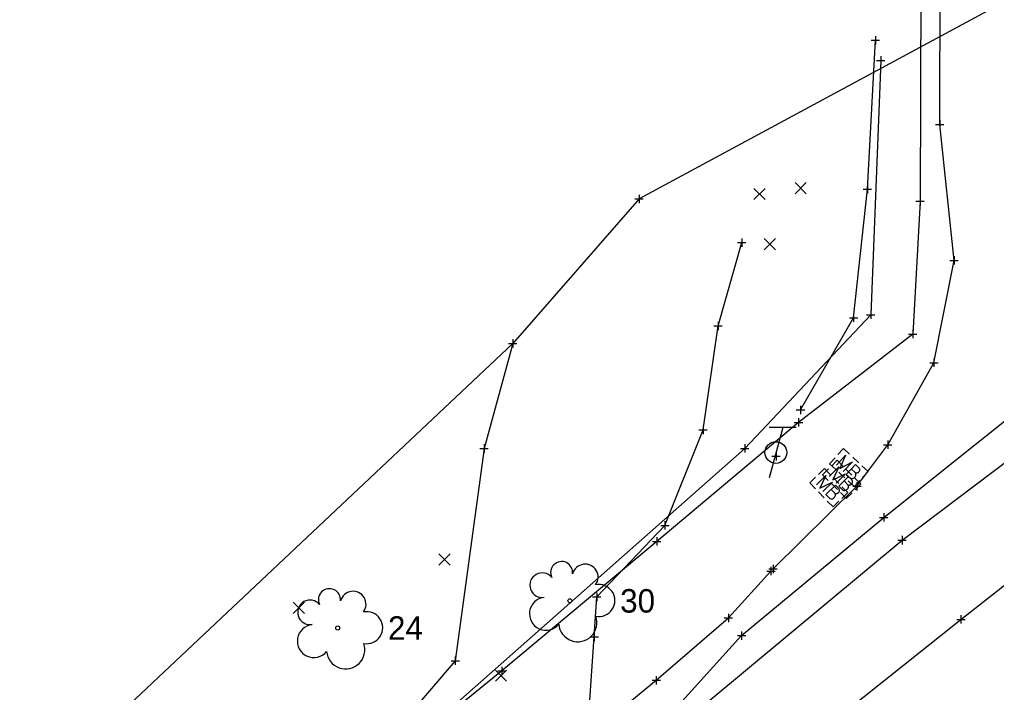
# Model space of a CAD drawing. Extents: x 2184635 to 2185378, y 369880 to 370486.
# Drawn here: x 2184907.9 to 2185024.5, y 370185.8 to 370266 of the extents above; entities that cross this region are included whole.
import ezdxf

# ---------------------------------------------------------------- set-up
doc = ezdxf.new("R2010")
doc.units = 0
for name, color, linetype in [('_CIVIL_CONSTRUCTION', 7, 'Continuous'), ('GE_X_Alignment', 7, 'Continuous'), ('GE_X_Alignment_100_Distances', 7, 'Continuous'), ('PM_X_CL_Pass_Proh_Rt', 7, 'Continuous'), ('PM_X_Edge_Line', 7, 'Continuous'), ('PV_X_COP', 7, 'Continuous'), ('PV_X_Driveway', 7, 'Continuous'), ('PV_X_EOP', 7, 'Continuous'), ('PV_X_Shoulder', 7, 'Continuous'), ('RD_X_Fence', 7, 'Continuous'), ('RW_X_CL', 7, 'Continuous'), ('RW_X_CL_100_Cardinal_Points', 7, 'Continuous'), ('RW_X_CL_100_Distances', 7, 'Continuous'), ('SV_X_Break_Lines', 7, 'Continuous'), ('SV_X_Terrain_Boundary', 7, 'Continuous'), ('VG_X_Text', 7, 'Continuous'), ('VG_X_Tree_Line_Lt', 7, 'Continuous')]:
    doc.layers.add(name, color=color, linetype=linetype)

msp = doc.modelspace()

# ---------------------------------------------------------------- linework, layer by layer
at = {"layer": '_CIVIL_CONSTRUCTION'}
for p, q in [((2185000.47, 370245.24), (2185001.8, 370246.58)), ((2185000.47, 370246.58), (2185001.8, 370245.24)), ((2184995.55, 370244.55), (2184996.88, 370245.89)), ((2184995.55, 370245.89), (2184996.88, 370244.55)), ((2184996.77, 370238.57), (2184998.11, 370239.9)), ((2184996.77, 370239.9), (2184998.11, 370238.57)), ((2184957.94, 370200.95), (2184959.27, 370202.28)), ((2184957.94, 370202.28), (2184959.27, 370200.95)), ((2184940.54, 370195.19), (2184941.88, 370196.52)), ((2184940.54, 370196.52), (2184941.88, 370195.19)), ((2184964.7, 370187.1), (2184966.03, 370188.43)), ((2184964.7, 370188.43), (2184966.03, 370187.1))]:
    msp.add_line(p, q, dxfattribs=at)
at = {"layer": 'GE_X_Alignment'}
for centre in [(2184973.58, 370196.69), (2184945.86, 370193.45)]:
    msp.add_circle(centre, 0.24, dxfattribs=at)
for centre, radius, start, end in [((2184972.59, 370200.06), 1.32, 354.0047, 205.9741), ((2184975.4, 370199.52), 1.55, 323.83, 165.0376), ((2184970.27, 370198.56), 1.47, 39.0625, 279.5412), ((2184977.04, 370196.73), 1.91, 259.1453, 101.4596), ((2184944.88, 370196.82), 1.32, 354.0047, 205.9741), ((2184947.69, 370196.28), 1.55, 323.83, 165.0376), ((2184942.55, 370195.32), 1.47, 39.0625, 279.5412), ((2184970.72, 370195.15), 1.97, 96.1722, 320.5737), ((2184949.32, 370193.49), 1.91, 259.1453, 101.4596), ((2184943.01, 370191.9), 1.97, 96.1722, 320.5737), ((2184974.52, 370194.09), 2.28, 184.9476, 19.4572), ((2184946.81, 370190.85), 2.28, 184.9476, 19.4572)]:
    msp.add_arc(centre, radius, start, end, dxfattribs=at)
at = {"layer": 'GE_X_Alignment_100_Distances'}
msp.add_lwpolyline([(2184659.61, 369925.95), (2184700.37, 369957.79), (2184738.5, 369988.63), (2184777.83, 370020.25), (2184816.43, 370051.35), (2184855.55, 370082.58), (2184897, 370115.36), (2184935.6, 370145.23), (2184944.92, 370153.84), (2184957.87, 370164.57), (2184961.94, 370169.28), (2184974.73, 370179.72), (2184983.89, 370187.22), (2184992.5, 370194.66), (2184997.57, 370200.25)], dxfattribs=at)
at = {"layer": 'PM_X_CL_Pass_Proh_Rt'}
msp.add_lwpolyline([(2184772.08, 369998.33), (2184786.36, 370009.44), (2184824.96, 370040.26), (2184864.24, 370071.89), (2184905.97, 370104.8), (2184943.4, 370134), (2184983.48, 370165.21), (2185020.26, 370194.47), (2185061.22, 370226.63), (2185099.74, 370257.78), (2185139.18, 370289.51), (2185177.35, 370320.31), (2185216.05, 370351.8), (2185254.73, 370383.45)], dxfattribs=at)
at = {"layer": 'PM_X_Edge_Line'}
msp.add_lwpolyline([(2184661.52, 369922.95), (2184702.12, 369955.42), (2184740.46, 369986.31), (2184779.79, 370018.04), (2184818.42, 370048.83), (2184857.46, 370080.19), (2184899.14, 370112.8), (2184937.36, 370142.73), (2184976.78, 370173.64), (2185013.23, 370203.93), (2185054.74, 370235.21), (2185093.13, 370266.2), (2185132.9, 370298.21), (2185170.88, 370328.99), (2185209.71, 370360.44), (2185248.24, 370392.05)], dxfattribs=at)
at = {"layer": 'PV_X_COP'}
msp.add_lwpolyline([(2184667.94, 369914.54), (2184708.44, 369946.75), (2184746.44, 369977.52), (2184786.36, 370009.44), (2184824.96, 370040.26), (2184864.24, 370071.89), (2184905.97, 370104.8), (2184943.4, 370134), (2184983.48, 370165.21), (2185020.26, 370194.47), (2185061.22, 370226.63), (2185099.74, 370257.78), (2185139.18, 370289.51), (2185177.35, 370320.31), (2185216.05, 370351.8), (2185254.68, 370383.2)], dxfattribs=at)
at = {"layer": 'PV_X_Driveway'}
msp.add_lwpolyline([(2184997.84, 370200.5), (2185007.85, 370210.36), (2185011.52, 370215.32), (2185017.04, 370225.09), (2185019.44, 370237.31), (2185017.73, 370253.53), (2185017.77, 370271.02), (2185017.83, 370279.15)], dxfattribs=at)
at = {"layer": 'PV_X_EOP'}
msp.add_lwpolyline([(2184661.56, 369922.86), (2184702.12, 369955.42), (2184740.46, 369986.31), (2184779.79, 370018.04), (2184818.42, 370048.83), (2184857.46, 370080.19), (2184899.14, 370112.8), (2184937.36, 370142.73), (2184976.78, 370173.64), (2185013.23, 370203.93), (2185054.74, 370235.21), (2185093.13, 370266.2), (2185132.9, 370298.21), (2185170.88, 370328.99), (2185209.71, 370360.44), (2185248.18, 370392.04)], dxfattribs=at)
at = {"layer": 'PV_X_Shoulder'}
msp.add_lwpolyline([(2184660.62, 369924.65), (2184701.18, 369956.99), (2184739.31, 369987.69), (2184778.66, 370019.08), (2184817.14, 370050.2), (2184856.42, 370081.4), (2184897.96, 370114.28), (2184936.32, 370143.73), (2184975.81, 370174.82), (2184986.61, 370184.31), (2184994.08, 370192.55), (2185011.04, 370206.65), (2185033.17, 370224.29), (2185051.81, 370238.9), (2185062.89, 370246.96), (2185064.96, 370248), (2185067.33, 370248.11), (2185092.06, 370267.24), (2185132, 370299.51), (2185169.97, 370330.25), (2185208.84, 370361.61), (2185247.24, 370392.98)], dxfattribs=at)
at = {"layer": 'RD_X_Fence'}
msp.add_lwpolyline([(2185015.2, 370283.15), (2185015.46, 370270.12), (2185015.39, 370244.36), (2185014.51, 370228.51), (2185000.87, 370217.98), (2184983.95, 370203.78), (2184965.47, 370188.33), (2184938.37, 370166.29), (2184905.93, 370138.5), (2184906.07, 370146.45), (2184906.53, 370163.61)], dxfattribs=at)
at = {"layer": 'RW_X_CL'}
for p, q in [((2185010.05, 370264.07), (2185010.05, 370263.07)), ((2185009.55, 370263.57), (2185010.55, 370263.57)), ((2185010.05, 370263.57), (2185010.05, 370263.57)), ((2185010.68, 370261.65), (2185010.68, 370260.65)), ((2185010.18, 370261.15), (2185011.18, 370261.15)), ((2185010.68, 370261.15), (2185010.68, 370261.15)), ((2185017.23, 370253.53), (2185018.23, 370253.53)), ((2185017.73, 370254.03), (2185017.73, 370253.03)), ((2185017.73, 370253.53), (2185017.73, 370253.53)), ((2185008.59, 370245.79), (2185009.59, 370245.79)), ((2185009.09, 370246.29), (2185009.09, 370245.29)), ((2185009.09, 370245.79), (2185009.09, 370245.79)), ((2184981.34, 370244.63), (2184982.34, 370244.63)), ((2184981.84, 370245.13), (2184981.84, 370244.13)), ((2184981.84, 370244.63), (2184981.84, 370244.63)), ((2185014.89, 370244.36), (2185015.89, 370244.36)), ((2185015.39, 370244.86), (2185015.39, 370243.86)), ((2185015.39, 370244.36), (2185015.39, 370244.36)), ((2184993.6, 370239.43), (2184994.6, 370239.43)), ((2184994.1, 370239.93), (2184994.1, 370238.93)), ((2184994.1, 370239.43), (2184994.1, 370239.43)), ((2185018.94, 370237.31), (2185019.94, 370237.31)), ((2185019.44, 370237.81), (2185019.44, 370236.81)), ((2185019.44, 370237.31), (2185019.44, 370237.31)), ((2185009.5, 370231.33), (2185009.5, 370230.33)), ((2185006.95, 370230.47), (2185007.95, 370230.47)), ((2185007.45, 370230.97), (2185007.45, 370229.97)), ((2185007.45, 370230.47), (2185007.45, 370230.47)), ((2185009, 370230.83), (2185010, 370230.83)), ((2185009.5, 370230.83), (2185009.5, 370230.83)), ((2184990.77, 370229.49), (2184991.77, 370229.49)), ((2184991.27, 370229.99), (2184991.27, 370228.99)), ((2184991.27, 370229.49), (2184991.27, 370229.49)), ((2185014.51, 370229.01), (2185014.51, 370228.01)), ((2184966.76, 370227.91), (2184966.76, 370226.91)), ((2185014.01, 370228.51), (2185015.01, 370228.51)), ((2185014.51, 370228.51), (2185014.51, 370228.51)), ((2184966.26, 370227.41), (2184967.26, 370227.41)), ((2184966.76, 370227.41), (2184966.76, 370227.41)), ((2185017.04, 370225.59), (2185017.04, 370224.59)), ((2185016.54, 370225.09), (2185017.54, 370225.09)), ((2185017.04, 370225.09), (2185017.04, 370225.09)), ((2185001.11, 370219.96), (2185001.11, 370218.96)), ((2185000.61, 370219.46), (2185001.61, 370219.46)), ((2185000.87, 370218.48), (2185000.87, 370217.48)), ((2185001.11, 370219.46), (2185001.11, 370219.46)), ((2184989.47, 370217.58), (2184989.47, 370216.58)), ((2185000.37, 370217.98), (2185001.37, 370217.98)), ((2185000.87, 370217.98), (2185000.87, 370217.98)), ((2184988.97, 370217.08), (2184989.97, 370217.08)), ((2184989.47, 370217.08), (2184989.47, 370217.08)), ((2184962.84, 370214.87), (2184963.84, 370214.87)), ((2184963.34, 370215.37), (2184963.34, 370214.37)), ((2184963.34, 370214.87), (2184963.34, 370214.87)), ((2184993.95, 370214.87), (2184994.95, 370214.87)), ((2184994.45, 370215.37), (2184994.45, 370214.37)), ((2184994.45, 370214.87), (2184994.45, 370214.87)), ((2185011.02, 370215.32), (2185012.02, 370215.32)), ((2185011.52, 370215.82), (2185011.52, 370214.82)), ((2185011.52, 370215.32), (2185011.52, 370215.32)), ((2184997.7, 370213.94), (2184998.7, 370213.94)), ((2184998.2, 370214.44), (2184998.2, 370213.44)), ((2184998.2, 370213.94), (2184998.2, 370213.94)), ((2185007.35, 370210.36), (2185008.35, 370210.36)), ((2185007.85, 370210.86), (2185007.85, 370209.86)), ((2185007.85, 370210.36), (2185007.85, 370210.36)), ((2185011.04, 370207.15), (2185011.04, 370206.15)), ((2184984.42, 370205.69), (2184985.42, 370205.69)), ((2184984.92, 370206.19), (2184984.92, 370205.19)), ((2184984.92, 370205.69), (2184984.92, 370205.69)), ((2185010.54, 370206.65), (2185011.54, 370206.65)), ((2185011.04, 370206.65), (2185011.04, 370206.65)), ((2185013.23, 370204.43), (2185013.23, 370203.43)), ((2185013.23, 370204.43), (2185013.23, 370203.43)), ((2184983.45, 370203.78), (2184984.45, 370203.78)), ((2184983.95, 370204.28), (2184983.95, 370203.28)), ((2184983.95, 370203.78), (2184983.95, 370203.78)), ((2185012.73, 370203.93), (2185013.73, 370203.93)), ((2185012.73, 370203.93), (2185013.73, 370203.93)), ((2185013.23, 370203.93), (2185013.23, 370203.93)), ((2185013.23, 370203.93), (2185013.23, 370203.93)), ((2184997.84, 370201), (2184997.84, 370200)), ((2184997.07, 370200.25), (2184998.07, 370200.25)), ((2184997.34, 370200.5), (2184998.34, 370200.5)), ((2184997.57, 370200.75), (2184997.57, 370199.75)), ((2184997.57, 370200.25), (2184997.57, 370200.25)), ((2184997.84, 370200.5), (2184997.84, 370200.5)), ((2184976.78, 370197.65), (2184976.78, 370196.65)), ((2184976.28, 370197.15), (2184977.28, 370197.15)), ((2184976.78, 370197.15), (2184976.78, 370197.15)), ((2184992.5, 370195.16), (2184992.5, 370194.16)), ((2184992, 370194.66), (2184993, 370194.66)), ((2184992.5, 370194.66), (2184992.5, 370194.66)), ((2185019.76, 370194.47), (2185020.76, 370194.47)), ((2185019.76, 370194.47), (2185020.76, 370194.47)), ((2185020.26, 370194.97), (2185020.26, 370193.97)), ((2185020.26, 370194.97), (2185020.26, 370193.97)), ((2185020.26, 370194.47), (2185020.26, 370194.47)), ((2185020.26, 370194.47), (2185020.26, 370194.47)), ((2184976.49, 370192.88), (2184976.49, 370191.88)), ((2184994.08, 370193.05), (2184994.08, 370192.05)), ((2184975.99, 370192.38), (2184976.99, 370192.38)), ((2184976.49, 370192.38), (2184976.49, 370192.38)), ((2184993.58, 370192.55), (2184994.58, 370192.55)), ((2184994.08, 370192.55), (2184994.08, 370192.55)), ((2184959.4, 370189.55), (2184960.4, 370189.55)), ((2184959.9, 370190.05), (2184959.9, 370189.05)), ((2184959.9, 370189.55), (2184959.9, 370189.55)), ((2184964.97, 370188.33), (2184965.97, 370188.33)), ((2184965.47, 370188.83), (2184965.47, 370187.83)), ((2184965.47, 370188.33), (2184965.47, 370188.33)), ((2184983.39, 370187.22), (2184984.39, 370187.22)), ((2184983.89, 370187.72), (2184983.89, 370186.72)), ((2184983.89, 370187.22), (2184983.89, 370187.22))]:
    msp.add_line(p, q, dxfattribs=at)
at = {"layer": 'RW_X_CL_100_Cardinal_Points'}
for p, q in [((2185007.34, 370213.83), (2185008.07, 370213.15)), ((2185006.88, 370212.59), (2185006.88, 370212.59)), ((2185005, 370211.4), (2185005.7, 370210.68)), ((2185005.67, 370212.04), (2185006.41, 370211.36)), ((2185006.53, 370212.41), (2185007.24, 370211.7)), ((2185004.48, 370210.18), (2185004.48, 370210.18)), ((2185004.8, 370210.68), (2185005.51, 370209.97)), ((2185006.03, 370211.18), (2185006.03, 370211.18)), ((2185003.25, 370209.69), (2185003.95, 370208.97))]:
    msp.add_line(p, q, dxfattribs=at)
for points in [[(2185005.58, 370214.13), (2185006.24, 370214.85), (2185006.96, 370214.19)], [(2185005.29, 370212.39), (2185004.58, 370213.05), (2185005.24, 370213.76)], [(2185005.39, 370212.88), (2185006.47, 370214.06), (2185005.81, 370212.49), (2185007.3, 370213.29), (2185006.22, 370212.11)], [(2185004.54, 370211.53), (2185005.68, 370212.66), (2185004.95, 370211.12), (2185006.48, 370211.86), (2185005.35, 370210.73)], [(2185004.79, 370212.77), (2185005.48, 370213.46), (2185006.16, 370212.77)], [(2185007.68, 370211.95), (2185007.77, 370211.95), (2185007.82, 370211.95), (2185007.86, 370211.96), (2185007.89, 370211.97), (2185007.94, 370211.99), (2185007.98, 370212.01), (2185008.06, 370212.06), (2185008.08, 370212.09), (2185008.12, 370212.12), (2185008.16, 370212.19), (2185008.18, 370212.25), (2185008.19, 370212.31), (2185008.18, 370212.39), (2185008.16, 370212.45), (2185008.15, 370212.47), (2185008.12, 370212.53), (2185007.67, 370212.95), (2185006.58, 370211.78), (2185007.09, 370211.31), (2185007.18, 370211.29), (2185007.28, 370211.28), (2185007.4, 370211.31), (2185007.5, 370211.37), (2185007.59, 370211.44), (2185007.64, 370211.5), (2185007.67, 370211.57), (2185007.71, 370211.69), (2185007.72, 370211.79), (2185007.68, 370211.95), (2185007.17, 370212.42)], [(2185008.45, 370212.8), (2185009.18, 370212.13), (2185008.52, 370211.41)], [(2185002.89, 370210.06), (2185002.21, 370210.76), (2185002.9, 370211.43)], [(2185003, 370210.55), (2185004.15, 370211.66), (2185003.41, 370210.13), (2185004.94, 370210.85), (2185003.79, 370209.73)], [(2185003.26, 370211.78), (2185003.96, 370212.46), (2185004.64, 370211.77)], [(2185004.43, 370211.05), (2185003.75, 370211.73), (2185004.44, 370212.42)], [(2185006.8, 370210.51), (2185006.89, 370210.51), (2185006.94, 370210.51), (2185006.99, 370210.52), (2185007.01, 370210.53), (2185007.07, 370210.54), (2185007.1, 370210.56), (2185007.18, 370210.61), (2185007.21, 370210.63), (2185007.24, 370210.67), (2185007.29, 370210.73), (2185007.32, 370210.79), (2185007.32, 370210.86), (2185007.32, 370210.94), (2185007.3, 370210.99), (2185007.29, 370211.02), (2185007.26, 370211.08), (2185006.83, 370211.52), (2185005.69, 370210.38), (2185006.18, 370209.89), (2185006.28, 370209.87), (2185006.38, 370209.86), (2185006.5, 370209.89), (2185006.6, 370209.94), (2185006.69, 370210.01), (2185006.74, 370210.06), (2185006.78, 370210.13), (2185006.83, 370210.25), (2185006.83, 370210.35), (2185006.8, 370210.51), (2185006.31, 370211)], [(2185005.24, 370209.49), (2185005.33, 370209.49), (2185005.38, 370209.49), (2185005.43, 370209.5), (2185005.46, 370209.51), (2185005.51, 370209.53), (2185005.55, 370209.54), (2185005.63, 370209.59), (2185005.65, 370209.61), (2185005.69, 370209.65), (2185005.73, 370209.71), (2185005.76, 370209.77), (2185005.77, 370209.83), (2185005.76, 370209.91), (2185005.75, 370209.97), (2185005.74, 370209.99), (2185005.71, 370210.06), (2185005.28, 370210.5), (2185004.14, 370209.38), (2185004.62, 370208.89), (2185004.72, 370208.86), (2185004.81, 370208.85), (2185004.93, 370208.87), (2185005.04, 370208.93), (2185005.13, 370209), (2185005.18, 370209.05), (2185005.22, 370209.12), (2185005.27, 370209.23), (2185005.28, 370209.33), (2185005.24, 370209.49), (2185004.76, 370209.99)], [(2185006.06, 370210.31), (2185006.75, 370209.6), (2185006.06, 370208.92)], [(2185008.18, 370211.05), (2185007.52, 370210.33), (2185006.79, 370211.01)], [(2185007.6, 370211.33), (2185008.31, 370210.63), (2185007.62, 370209.95)], [(2185007.26, 370209.59), (2185006.58, 370208.9), (2185005.87, 370209.61)], [(2185005.69, 370208.57), (2185005, 370207.89), (2185004.31, 370208.6)]]:
    msp.add_lwpolyline(points, dxfattribs=at)
at = {"layer": 'RW_X_CL_100_Distances'}
for p, q in [((2184998.98, 370217.38), (2184997.37, 370211.38)), ((2185000.58, 370217.38), (2184997.38, 370217.38))]:
    msp.add_line(p, q, dxfattribs=at)
msp.add_circle((2184998.17, 370214.38), 1.3, dxfattribs=at)
at = {"layer": 'SV_X_Break_Lines'}
for points in [[(2185001.11, 370219.46), (2185007.45, 370230.47), (2185009.09, 370245.79), (2185010.05, 370263.57)], [(2184981.84, 370244.63), (2184966.76, 370227.41), (2184963.34, 370214.87), (2184959.9, 370189.55), (2184954, 370182.64), (2184940.54, 370172.41), (2184922.27, 370158.19)], [(2184968.56, 370183.02), (2184975.88, 370183.63), (2184976.49, 370192.38), (2184976.78, 370197.15), (2184984.92, 370205.69), (2184989.47, 370217.08), (2184991.27, 370229.49), (2184994.1, 370239.43)]]:
    msp.add_lwpolyline(points, dxfattribs=at)
at = {"layer": 'SV_X_Terrain_Boundary'}
msp.add_lwpolyline([(2185048.79, 370280.75), (2184981.84, 370244.63), (2184966.76, 370227.41), (2184901.88, 370166.35), (2184859.95, 370200.01), (2184846.28, 370205.14), (2184825.04, 370216.07), (2184786.25, 370161.28), (2184768.88, 370142.96), (2184755.89, 370127.05), (2184768.66, 370083.99), (2184723.55, 370028.87), (2184709.4, 370017.08), (2184650.83, 369961.55), (2184636.07, 369950.04)], dxfattribs=at)
at = {"layer": 'VG_X_Tree_Line_Lt'}
msp.add_lwpolyline([(2185010.68, 370261.15), (2185009.5, 370230.83), (2184994.45, 370214.87), (2184919.45, 370148.63), (2184883.31, 370122.36), (2184845.08, 370084.67), (2184789.48, 370110.6), (2184762.67, 370135.82)], dxfattribs=at)

# ---------------------------------------------------------------- texts
at = {"layer": 'VG_X_Text'}
for s, p in [('30', (2184979.58, 370195.29)), ('24', (2184951.86, 370192.05))]:
    msp.add_text(s, height=2.8, dxfattribs=at).set_placement(p)

doc.saveas('drawing.dxf')
